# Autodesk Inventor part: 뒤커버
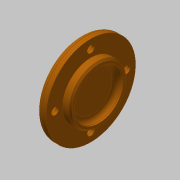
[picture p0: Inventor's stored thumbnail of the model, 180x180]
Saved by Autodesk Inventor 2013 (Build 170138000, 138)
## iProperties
Created: 2019-06
Part Number: 뒤커버
Material: 알루미늄 6061
Document SubType Name: Modeling
Designer: mduedu
Density: 1 g/cm^3
Author: mduedu
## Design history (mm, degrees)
sketch "스케치1"
  geometry: L1 (0, 0)-(-5, 0); L2 (-5, 0)-(-5, 17.5); L3 (-5, 17.5)-(0, 17.5); L4 (0, 17.5)-(0, 0); L5 (-5, 0)-(-11, 0); L6 (-11, 0)-(-11, 27.5); L7 (-11, 27.5)-(-5, 27.5); L8 (-5, 27.5)-(-5, 0)
  constraints: 16 end point, 4 parallel, 2 horizontal, 2 perpendicular
  dimensions: "d0" = 11 distance between parallel lines of L4 L6; "d2" = 5 distance of L2.end L3.end; "d3" = 55 diameter of L7 L5; "d4" = 35 diameter of L3 L1
revolve "회전1" sketch "스케치1" stored, may be unused: angle "d5" = 90 deg
sketch "스케치2"
  geometry: C1 r 15 at (0, 0); 1 further point
  constraints: 1 centre point, 1 coincident
  dimensions: "d6" = 30 diameter of C1
extrude "돌출1" cut sketch "스케치2" distance "d7" = 4; taper "d8" = 0 deg
fillet "모깎기1" dims "d9" = 3
fillet "모깎기2" dims "d10" = 3
chamfer "모따기1" distance "d11" = 1; stored, may be unused: second distance "d12" = 2, angle "d13" = 45 deg
sketch "스케치3" dims "d14" = 44
  geometry: 3 further points
  constraints: 2 vertical alignment, 1 coincident, 2 other
hole "구멍1" sketch "스케치3" at (0, 22) diameter "d15" = 4.5; stored, may be unused: countersink angle "d19" = 90 deg, drill point angle "d21" = 118 deg; dims "d16" = 6, "d17" = 8, "d18" = 4.4, "d20" = 8
node "솔리드1"
pattern_circular "원형 패턴1" dims angle "d23" = 360 deg
